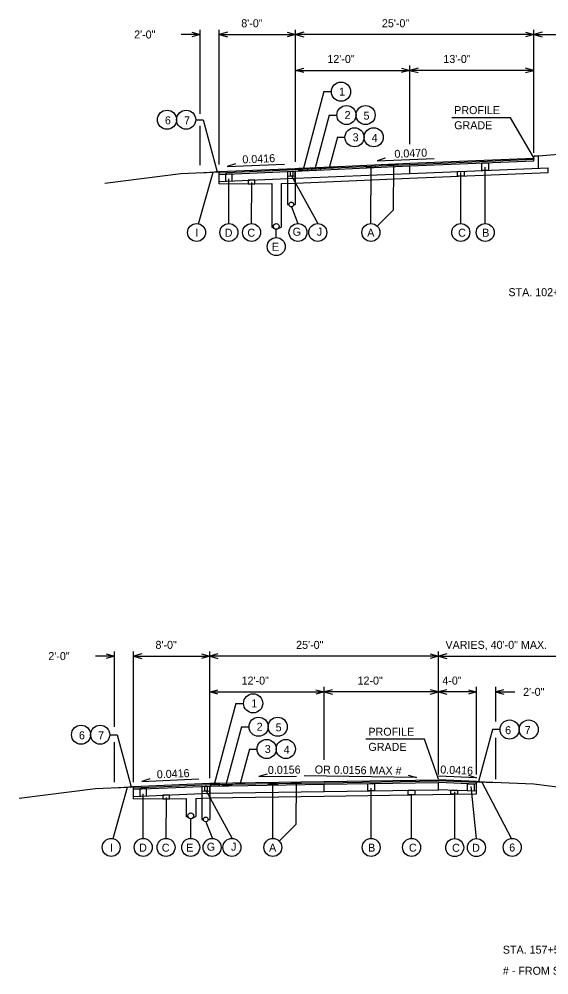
# Model space of a CAD drawing. Extents: x -161 to 291, y -369 to 173.
# Drawn here: x -103.7 to -66.6, y 105 to 171.9 of the extents above; entities that cross this region are included whole.
import ezdxf

# ---------------------------------------------------------------- set-up
doc = ezdxf.new("R2010")
doc.units = 0
for name, color, linetype in [('Level 11', 7, 'Continuous'), ('Level 16', 7, 'Continuous'), ('Level 21', 7, 'Continuous'), ('Level 26', 7, 'Continuous'), ('SH_Text', 7, 'Continuous')]:
    doc.layers.add(name, color=color, linetype=linetype)

msp = doc.modelspace()

# ---------------------------------------------------------------- linework, layer by layer
at = {"layer": 'Level 11'}
for p, q in [((-63.032, 162.651), (-67.366, 162.289)), ((-67.699, 162.065), (-67.699, 162.234)), ((-67.365, 162.289), (-67.643, 162.289)), ((-67.365, 161.445), (-67.365, 162.289)), ((-84.935, 161.209), (-84.935, 158.898)), ((-84.379, 160.733), (-84.379, 161.232)), ((-84.379, 161.232), (-84.379, 158.898)), ((-76.365, 161.068), (-76.365, 161.593)), ((-76.363, 161.068), (-66.697, 161.473)), ((-66.699, 161.14), (-66.699, 161.473)), ((-97.713, 160.396), (-92.379, 161.063)), ((-92.379, 161.063), (-89.713, 161.175)), ((-89.713, 160.343), (-89.713, 161.006)), ((-89.71, 160.51), (-84.377, 160.733)), ((-84.935, 160.875), (-84.379, 160.898)), ((-84.363, 160.733), (-76.363, 161.068)), ((-84.363, 160.4), (-76.363, 160.735)), ((-76.363, 160.735), (-66.699, 161.14)), ((-89.712, 160.343), (-86.031, 160.356)), ((-86.031, 160.356), (-86.031, 157.319)), ((-85.364, 160.358), (-85.364, 157.312)), ((-85.362, 160.358), (-84.363, 160.4)), ((-84.935, 158.898), (-84.824, 158.898)), ((-84.49, 158.898), (-84.379, 158.898)), ((-85.816, 157.192), (-86.031, 157.319)), ((-85.622, 157.184), (-85.364, 157.312)), ((-74.365, 117.946), (-74.365, 118.445)), ((-74.365, 118), (-74.365, 118.445)), ((-67.699, 118.332), (-71.699, 118.5)), ((-103.699, 117.362), (-98.365, 118.029)), ((-98.365, 118.029), (-95.699, 118.14)), ((-95.699, 117.309), (-95.699, 117.973)), ((-90.921, 118.174), (-90.921, 115.864)), ((-90.921, 117.841), (-90.365, 117.864)), ((-90.365, 117.699), (-90.365, 118.198)), ((-90.365, 117.699), (-90.365, 118.198)), ((-90.365, 118.198), (-90.365, 115.864)), ((-90.355, 117.699), (-82.355, 117.823)), ((-82.365, 117.823), (-82.365, 118.321)), ((-82.355, 117.823), (-74.365, 117.946)), ((-71.701, 117.835), (-74.368, 117.947)), ((-71.699, 117.654), (-71.699, 118.333)), ((-65.513, 118.059), (-67.699, 118.332)), ((-95.699, 117.309), (-92.017, 117.322)), ((-95.696, 117.475), (-90.363, 117.699)), ((-92.017, 117.322), (-92.017, 116.073)), ((-91.35, 117.324), (-90.349, 117.366)), ((-91.35, 117.324), (-91.35, 116.066)), ((-90.35, 117.366), (-82.355, 117.489)), ((-82.355, 117.49), (-71.699, 117.654)), ((-91.802, 115.946), (-92.017, 116.073)), ((-91.609, 115.938), (-91.35, 116.066)), ((-90.921, 115.864), (-90.81, 115.864)), ((-90.476, 115.864), (-90.365, 115.864))]:
    msp.add_line(p, q, dxfattribs=at)
for centre, radius in [((-84.657, 158.898), 0.167), ((-85.712, 157.366), 0.203), ((-91.699, 116.12), 0.203), ((-90.643, 115.864), 0.167)]:
    msp.add_circle(centre, radius, dxfattribs=at)
msp.add_arc((-67.644, 162.234), 0.0553, 90, 180, dxfattribs=at)
at = {"layer": 'Level 16'}
for p, q in [((-79.091, 157.569), (-79.081, 161.507)), ((-77.505, 158.525), (-77.497, 161.695)), ((-71.094, 157.569), (-71.094, 161.501)), ((-91.143, 157.551), (-90.131, 161.16)), ((-89.028, 157.569), (-89.028, 160.691)), ((-84.639, 160.896), (-82.809, 157.569)), ((-72.808, 157.569), (-72.808, 161.144)), ((-87.437, 157.569), (-87.41, 160.438)), ((-84.657, 158.731), (-84.193, 157.569)), ((-78.646, 157.384), (-77.505, 158.525)), ((-85.712, 156.584), (-85.712, 157.163)), ((-84.313, 115.544), (-84.305, 118.447)), ((-69.265, 114.532), (-71.331, 118.497)), ((-97.129, 114.521), (-96.117, 118.126)), ((-90.625, 117.862), (-88.795, 114.534)), ((-85.953, 114.534), (-85.943, 118.351)), ((-79.075, 114.534), (-79.075, 118.049)), ((-73.232, 114.525), (-73.232, 117.786)), ((-71.716, 114.525), (-72.079, 118.175)), ((-95.014, 114.534), (-95.014, 117.657)), ((-93.423, 114.534), (-93.396, 117.403)), ((-76.249, 114.534), (-76.249, 117.643)), ((-91.699, 114.534), (-91.699, 115.917)), ((-90.643, 115.697), (-90.178, 114.534)), ((-85.507, 114.35), (-84.313, 115.544))]:
    msp.add_line(p, q, dxfattribs=at)
for points in [[(-73.042, 160.875), (-73.042, 161.209), (-72.576, 161.227), (-72.576, 160.894)], [(-71.328, 161.281), (-71.328, 161.805), (-70.863, 161.825), (-70.863, 161.301)], [(-88.795, 160.55), (-88.795, 161.049), (-89.262, 161.03), (-89.262, 160.531)], [(-87.205, 160.352), (-87.205, 160.615), (-87.671, 160.596), (-87.671, 160.352)], [(-94.781, 117.512), (-94.781, 118.015), (-95.248, 117.996), (-95.248, 117.493)], [(-79.309, 117.868), (-79.308, 118.365), (-78.843, 118.373), (-78.843, 117.875)], [(-76.483, 117.58), (-76.483, 117.913), (-76.015, 117.92), (-76.015, 117.587)], [(-73.503, 117.625), (-73.503, 117.91), (-73.037, 117.889), (-73.037, 117.633)], [(-72.328, 117.859), (-72.328, 118.361), (-71.86, 118.341), (-71.861, 117.84)], [(-93.191, 117.317), (-93.191, 117.58), (-93.657, 117.561), (-93.657, 117.317)]]:
    msp.add_lwpolyline(points, close=True, dxfattribs=at)
for centre in [(-91.29, 156.939), (-89.028, 156.939), (-87.437, 156.939), (-84.193, 156.939), (-82.809, 156.939), (-79.091, 156.939), (-72.808, 156.939), (-71.094, 156.939), (-85.712, 155.954), (-97.26, 113.904), (-95.015, 113.904), (-93.423, 113.904), (-91.699, 113.904), (-90.197, 113.904), (-88.814, 113.904), (-85.953, 113.904), (-79.075, 113.904), (-76.249, 113.904), (-73.232, 113.895), (-71.716, 113.895), (-69.205, 113.904)]:
    msp.add_circle(centre, 0.63, dxfattribs=at)
at = {"layer": 'Level 21'}
for p, q in [((-76.373, 161.786), (-67.699, 162.15)), ((-76.37, 161.7), (-67.699, 162.063)), ((-76.365, 161.593), (-67.699, 161.956)), ((-67.699, 162.15), (-67.699, 162.063)), ((-67.699, 161.956), (-67.699, 162.062)), ((-91.046, 161.119), (-89.713, 161.201)), ((-89.713, 161.201), (-84.387, 161.424)), ((-89.713, 161.115), (-84.384, 161.338)), ((-89.713, 161.008), (-84.379, 161.231)), ((-89.713, 161.201), (-89.713, 161.115)), ((-84.388, 161.425), (-76.374, 161.786)), ((-84.384, 161.338), (-76.37, 161.7)), ((-84.379, 161.232), (-76.365, 161.593)), ((-91.046, 161.119), (-89.713, 161.175)), ((-89.713, 161.008), (-89.713, 161.175)), ((-95.699, 118.167), (-90.349, 118.391)), ((-90.349, 118.391), (-82.368, 118.515)), ((-90.346, 118.308), (-82.367, 118.431)), ((-82.368, 118.515), (-74.363, 118.638)), ((-82.367, 118.431), (-74.364, 118.555)), ((-82.365, 118.321), (-74.365, 118.445)), ((-71.699, 118.333), (-74.365, 118.445)), ((-71.699, 118.443), (-74.364, 118.555)), ((-71.699, 118.527), (-74.363, 118.638)), ((-71.699, 118.527), (-71.699, 118.443)), ((-71.699, 118.527), (-70.365, 118.444)), ((-71.699, 118.5), (-70.365, 118.444)), ((-71.699, 118.333), (-71.699, 118.5)), ((-97.032, 118.084), (-95.699, 118.167)), ((-97.032, 118.084), (-95.699, 118.14)), ((-95.699, 118.084), (-90.346, 118.308)), ((-95.699, 117.974), (-90.365, 118.197)), ((-95.699, 118.167), (-95.699, 118.084)), ((-95.699, 117.974), (-95.699, 118.14)), ((-90.365, 118.198), (-82.365, 118.321))]:
    msp.add_line(p, q, dxfattribs=at)
at = {"layer": 'Level 26'}
for p, q in [((-91.032, 170.787), (-92.365, 170.787)), ((-91.032, 165.241), (-91.032, 171.121)), ((-89.699, 161.687), (-89.699, 171.121)), ((-89.699, 170.787), (-84.365, 170.787)), ((-84.365, 161.884), (-84.365, 171.121)), ((-67.699, 170.787), (-84.365, 170.787)), ((-67.699, 162.509), (-67.699, 171.121)), ((-67.699, 162.607), (-67.699, 171.121)), ((-67.699, 170.787), (-63.032, 170.787)), ((-76.365, 163.117), (-76.365, 168.636)), ((-84.365, 168.286), (-76.365, 168.286)), ((-67.699, 168.286), (-76.365, 168.286)), ((-69.333, 164.973), (-73.438, 164.973)), ((-67.73, 162.215), (-69.333, 164.973)), ((-91.032, 161.648), (-91.032, 164.398)), ((-97.032, 127.286), (-98.365, 127.286)), ((-97.032, 122.334), (-97.032, 127.62)), ((-95.699, 118.473), (-95.699, 127.62)), ((-95.699, 127.286), (-90.365, 127.286)), ((-90.365, 118.753), (-90.365, 127.62)), ((-74.365, 127.286), (-90.365, 127.286)), ((-74.365, 119.008), (-74.365, 127.62)), ((-74.365, 127.286), (-63.032, 127.286)), ((-82.365, 120.031), (-82.365, 125.135)), ((-71.699, 119.008), (-71.699, 125.135)), ((-70.365, 122.718), (-70.365, 125.135)), ((-90.365, 124.785), (-82.365, 124.785)), ((-74.365, 124.785), (-82.365, 124.785)), ((-71.699, 124.785), (-74.365, 124.785)), ((-70.365, 124.785), (-69.032, 124.785)), ((-97.032, 118.473), (-97.032, 121.275)), ((-75.333, 121.472), (-79.438, 121.472)), ((-74.365, 118.69), (-75.333, 121.472)), ((-70.365, 118.675), (-70.365, 121.573))]:
    msp.add_line(p, q, dxfattribs=at)
for points in [[(-91.611, 170.947), (-91.032, 170.787), (-91.611, 170.633)], [(-89.121, 170.947), (-89.699, 170.787), (-89.121, 170.633)], [(-84.943, 170.947), (-84.365, 170.787), (-84.943, 170.633)], [(-83.788, 170.947), (-84.365, 170.787), (-83.788, 170.633)], [(-68.276, 170.947), (-67.699, 170.787), (-68.276, 170.633)], [(-67.12, 170.947), (-67.699, 170.787), (-67.12, 170.633)], [(-67.121, 170.947), (-67.699, 170.787), (-67.121, 170.633)], [(-83.788, 168.127), (-84.365, 168.286), (-83.788, 168.44)], [(-76.943, 168.446), (-76.365, 168.286), (-76.943, 168.132)], [(-75.788, 168.446), (-76.365, 168.286), (-75.788, 168.132)], [(-68.276, 168.127), (-67.699, 168.286), (-68.276, 168.44)], [(-78.084, 162.13), (-78.654, 161.951), (-74.657, 162.121)], [(-88.568, 161.741), (-89.138, 161.563), (-85.136, 161.731)], [(-97.611, 127.446), (-97.032, 127.286), (-97.611, 127.132)], [(-95.121, 127.446), (-95.699, 127.286), (-95.121, 127.132)], [(-90.943, 127.446), (-90.365, 127.286), (-90.943, 127.132)], [(-89.788, 127.446), (-90.365, 127.286), (-89.788, 127.132)], [(-74.943, 127.446), (-74.365, 127.286), (-74.943, 127.132)], [(-73.787, 127.446), (-74.365, 127.286), (-73.787, 127.132)], [(-89.788, 124.626), (-90.365, 124.785), (-89.788, 124.939)], [(-82.943, 124.945), (-82.365, 124.785), (-82.943, 124.631)], [(-81.788, 124.945), (-82.365, 124.785), (-81.788, 124.631)], [(-74.943, 124.626), (-74.365, 124.785), (-74.943, 124.939)], [(-73.787, 124.945), (-74.365, 124.785), (-73.787, 124.631)], [(-72.278, 124.945), (-71.699, 124.785), (-72.278, 124.631)], [(-69.787, 124.945), (-70.365, 124.785), (-69.787, 124.631)], [(-94.554, 118.707), (-95.124, 118.529), (-91.122, 118.697)], [(-86.358, 119.022), (-86.933, 118.859), (-84.305, 118.899)], [(-76.485, 118.966), (-75.91, 118.803), (-83.757, 118.924)], [(-72.274, 118.955), (-71.704, 118.777), (-74.368, 118.888)]]:
    msp.add_lwpolyline(points, dxfattribs=at)
for points in [[(-89.776, 161.197), (-89.916, 161.189), (-89.914, 161.167), (-89.774, 161.175)], [(-84.717, 160.885), (-84.717, 161.218), (-84.561, 161.225), (-84.561, 160.892)], [(-84.135, 161.435), (-83.528, 161.464), (-83.524, 161.271), (-84.125, 161.243)], [(-83.235, 161.389), (-82.63, 161.415), (-82.629, 161.312), (-83.23, 161.287)], [(-82.266, 161.522), (-81.662, 161.548), (-81.661, 161.461), (-82.267, 161.434)], [(-79.398, 161.564), (-78.786, 161.593), (-78.785, 161.487), (-79.397, 161.459)], [(-77.823, 161.721), (-77.216, 161.75), (-77.216, 161.664), (-77.824, 161.635)], [(-90.302, 118.393), (-89.695, 118.403), (-89.697, 118.21), (-90.298, 118.2)], [(-88.544, 118.422), (-87.94, 118.433), (-87.941, 118.345), (-88.543, 118.333)], [(-84.631, 118.482), (-84.022, 118.491), (-84.022, 118.405), (-84.631, 118.396)], [(-71.654, 118.524), (-71.482, 118.513), (-71.483, 118.491), (-71.656, 118.502)], [(-95.767, 118.163), (-95.917, 118.154), (-95.916, 118.131), (-95.765, 118.14)], [(-90.703, 117.851), (-90.703, 118.184), (-90.547, 118.191), (-90.547, 117.858)], [(-89.474, 118.318), (-88.869, 118.328), (-88.87, 118.225), (-89.472, 118.215)], [(-86.258, 118.371), (-85.644, 118.38), (-85.644, 118.271), (-86.258, 118.262)]]:
    msp.add_lwpolyline(points, close=True, dxfattribs=at)
at = {"layer": 'SH_Text'}
for p, q in [((-82.382, 166.795), (-83.839, 161.359)), ((-82.382, 166.795), (-81.853, 166.795)), ((-91.348, 164.83), (-90.819, 164.83)), ((-90.819, 164.83), (-89.844, 161.193)), ((-82.001, 165.158), (-83.018, 161.362)), ((-82.001, 165.158), (-81.471, 165.158)), ((-81.437, 163.601), (-82.01, 161.465)), ((-81.437, 163.601), (-80.908, 163.601)), ((-88.529, 123.987), (-90.049, 118.312)), ((-88.529, 123.987), (-87.999, 123.987)), ((-97.361, 121.794), (-96.832, 121.794)), ((-96.832, 121.794), (-95.857, 118.157)), ((-88.147, 122.35), (-89.239, 118.277)), ((-88.147, 122.35), (-87.618, 122.35)), ((-70.591, 122.155), (-71.565, 118.518)), ((-70.061, 122.155), (-70.591, 122.155)), ((-87.583, 120.793), (-88.232, 118.374)), ((-87.583, 120.793), (-87.054, 120.793))]:
    msp.add_line(p, q, dxfattribs=at)
for centre in [(-81.184, 166.795), (-93.355, 164.83), (-92.017, 164.83), (-80.802, 165.158), (-79.464, 165.158), (-80.239, 163.601), (-78.9, 163.601), (-87.33, 123.987), (-99.368, 121.794), (-98.03, 121.794), (-86.949, 122.35), (-85.611, 122.35), (-69.392, 122.155), (-68.054, 122.155), (-86.385, 120.793), (-85.047, 120.793)]:
    msp.add_circle(centre, 0.669, dxfattribs=at)

# ---------------------------------------------------------------- texts
at = {"layer": 'Level 16'}
for s, p in [('I', (-91.371, 156.652)), ('D', (-89.318, 156.642)), ('C', (-87.732, 156.642)), ('G', (-84.566, 156.711)), ('J', (-82.874, 156.711)), ('A', (-79.352, 156.652)), ('C', (-72.99, 156.642)), ('B', (-71.307, 156.642)), ('E', (-86.021, 155.657)), ('I', (-97.341, 113.618)), ('D', (-95.304, 113.608)), ('C', (-93.718, 113.608)), ('E', (-92.007, 113.608)), ('G', (-90.571, 113.676)), ('J', (-88.879, 113.676)), ('A', (-86.214, 113.618)), ('B', (-79.287, 113.608)), ('C', (-76.431, 113.608)), ('C', (-73.414, 113.599)), ('D', (-72.014, 113.599)), ('6', (-69.418, 113.618))]:
    msp.add_text(s, height=0.56, dxfattribs=at).set_placement(p)
at = {"layer": 'Level 26'}
for s, p in [('8\'-0"', (-88.161, 171.303)), ('25\'-0"', (-78.322, 171.303)), ('2\'-0"', (-95.656, 170.515)), ('12\'-0"', (-82.138, 168.802)), ('13\'-0"', (-74.026, 168.802)), ('PROFILE ', (-73.266, 165.223)), ('GRADE', (-73.266, 164.163)), ('STA. 102+98.23 TO STA. 123+08.46', (-69.472, 152.482)), ('8\'-0"', (-94.161, 127.802)), ('25\'-0"', (-84.322, 127.802)), ('VARIES, 40\'-0" MAX.', (-73.878, 127.802)), ('2\'-0"', (-101.656, 127.014)), ('12\'-0"', (-88.138, 125.301)), ('12-0"', (-80.026, 125.301)), ('4-0"', (-74.095, 125.301)), ('2\'-0"', (-68.448, 124.513)), ('PROFILE ', (-79.266, 121.722)), ('GRADE', (-79.266, 120.662)), ('STA. 157+50.00 TO STA. 163+79.00', (-69.864, 106.469)), ('# - FROM STA 159+63 TO STA 163+79', (-69.863, 104.994))]:
    msp.add_text(s, height=0.56, dxfattribs=at).set_placement(p)
for s, rotation, p in [('0.0470', 2.42927, (-77.437, 162.158)), ('0.0416', 2.39878, (-88.071, 161.771)), ('0.0416', 2.39878, (-94.057, 118.736)), ('0.0156', 0.88554, (-86.295, 119.043)), ('OR 0.0156 MAX #', 359.11446, (-83.024, 119.081)), ('0.0416', 357.60122, (-74.249, 119.085))]:
    msp.add_text(s, height=0.56, rotation=rotation, dxfattribs=at).set_placement(p)
at = {"layer": 'SH_Text'}
for s, p in [('1', (-81.316, 166.514)), ('2', (-80.934, 164.878)), ('5', (-79.609, 164.837)), ('6', (-93.5, 164.508)), ('7', (-92.162, 164.504)), ('3', (-80.371, 163.321)), ('4', (-79.045, 163.28)), ('1', (-87.462, 123.706)), ('2', (-87.081, 122.07)), ('5', (-85.755, 122.029)), ('6', (-99.513, 121.472)), ('7', (-98.175, 121.468)), ('6', (-69.704, 121.829)), ('7', (-68.337, 121.833)), ('3', (-86.517, 120.513)), ('4', (-85.191, 120.472))]:
    msp.add_text(s, height=0.56, dxfattribs=at).set_placement(p)

doc.saveas('drawing.dxf')
